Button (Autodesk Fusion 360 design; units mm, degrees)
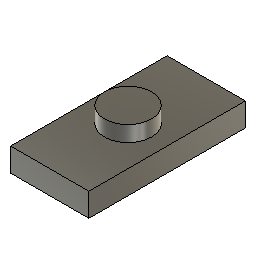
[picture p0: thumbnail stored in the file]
parameter "Hight_Z" = 0.3 (= "0.3 mm * Ratio") comment "for the Base"
parameter "Hight_B" = 0.2 (= "0.2 mm * Ratio") comment "button Hight"
sketch "Sketch1" plane through (0, 0, 0) normal (0, 0, 1) x axis (1, 0, 0)
  line L1 (-1, 0) -> (0, 0)
  line L2 (-1, 2) -> (-1, 0)
  line L3 (0, 2) -> (-1, 2)
  line L4 (0, 0) -> (0, 2)
  point P1 (0, 0)
  point P2 (0, 0)
  point P3 (-1, 0)
  point P5 (0, 2)
  horizontal L1
  vertical L2
  horizontal L3
  vertical L4
  coincident P1 P2
  dimension "d2" distance P2 P3 = 1 (= "( 1 * Ratio ) * 1 mm")
  dimension "d3" distance P2 P5 = 2 (= "( 2 * Ratio ) * 1 mm")
extrude "Extrude1" new body sketch "Sketch1" along normal blind 0.3 (= "Hight_Z")
sketch "Sketch2" plane through (0, 0, 0.3) normal (0, 0, 1) x axis (-1, 0, 0)
  line L1 (1, -2) -> (0, -2)
  line L2 (1, 0) -> (1, -2)
  line L3 (0, 0) -> (1, 0)
  line L4 (0, -2) -> (0, 0)
  circle C1 centre (0.5, -1) radius 0.3
  point P1 (0, 0)
  point P6 (0.5, -1)
  dimension "d8" diameter C1 = 0.6 (= "( 0.6 * Ratio ) * 1 mm")
  dimension "d11" distance P1 P6 = 1 (= "( 1 * Ratio ) * 1 mm")
  dimension "d12" distance P1 P6 = 0.5 (= "( 0.5 * Ratio ) * 1 mm")
extrude "Extrude2" add sketch "Sketch2" profile of C1 along normal blind 0.2 (= "Hight_B")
